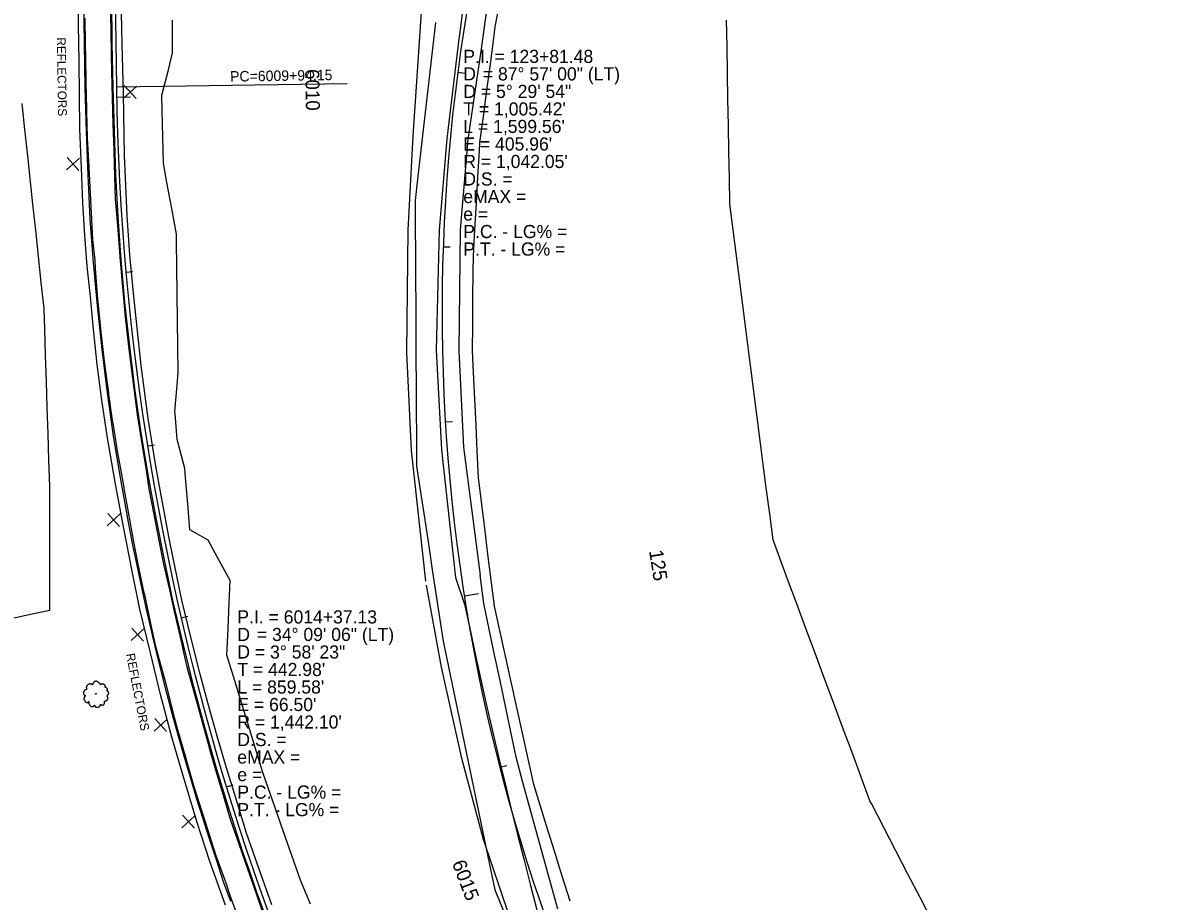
# Model space of a CAD drawing. Extents: x 2132221 to 2141942, y 535736 to 547298.
# Drawn here: x 2138929 to 2139580, y 539779 to 540281 of the extents above; entities that cross this region are included whole.
import ezdxf

# ---------------------------------------------------------------- set-up
doc = ezdxf.new("R2010")
doc.units = 0
for name, color, linetype in [('RD_EX_Conc', 7, 'Continuous'), ('RD_EX_Driveway', 7, 'Continuous'), ('RD_EX_Fence_Other', 7, 'Continuous'), ('RD_EX_Misc', 7, 'Continuous'), ('RD_EX_Misc_txCode', 7, 'Continuous'), ('RD_EX_Road', 7, 'Continuous'), ('RD_EX_VEG', 7, 'Continuous'), ('RD_HC_Cl', 7, 'Continuous'), ('RD_HC_Data', 7, 'Continuous'), ('RD_HC_Data_Tic', 7, 'Continuous'), ('RD_HC_TX_Sta50', 7, 'Continuous'), ('TOPO_E_TLIML-Line', 7, 'Continuous')]:
    doc.layers.add(name, color=color, linetype=linetype)

msp = doc.modelspace()

# ---------------------------------------------------------------- linework, layer by layer
at = {"layer": 'RD_EX_Conc'}
for points in [[(2139047.25, 539779.31), (2139043.17, 539790.54), (2139039.35, 539802.49), (2139034.85, 539815.62), (2139031.4, 539826.42), (2139027.85, 539837.63), (2139024.22, 539850.13), (2139020.67, 539862.18), (2139017.2, 539874.31), (2139013.81, 539886.56), (2139010.8, 539898.23), (2139007.9, 539909.44), (2139004.67, 539922.45), (2139001.65, 539935.51), (2138998.97, 539946.93), (2138996.49, 539958.58), (2138993.81, 539971.26), (2138991.38, 539982.77), (2138988.93, 539995.8), (2138984.43, 540020.27), (2138980.35, 540044.85), (2138976.92, 540069.62), (2138973.88, 540094.48), (2138971.21, 540119.3), (2138968.85, 540144.08), (2138967.01, 540168.84), (2138965.75, 540193.95), (2138964.84, 540218.87), (2138964.17, 540243.73), (2138963.78, 540268.99), (2138963.33, 540293.82)], [(2139066.43, 539772.72), (2139062.22, 539784.49), (2139058.14, 539796.38), (2139054.19, 539807.51), (2139046.48, 539831.19), (2139039.38, 539854.65), (2139032.53, 539878.81), (2139026.07, 539902.54), (2139020.18, 539925.86), (2139014.42, 539950.29), (2139009.36, 539974.37), (2139004.62, 539998.3), (2139000.1, 540022.95), (2138995.99, 540048.15), (2138992.44, 540072.16), (2138989.64, 540096.3), (2138986.8, 540121.15), (2138984.71, 540145.54), (2138982.92, 540170.05), (2138981.64, 540194.31), (2138980.81, 540219.3), (2138980.09, 540244.21), (2138979.59, 540269.04), (2138979.26, 540294.49)]]:
    msp.add_lwpolyline(points, dxfattribs=at)
at = {"layer": 'RD_EX_Driveway'}
for points in [[(2139375.47, 540750.48), (2139341.92, 540703.66), (2139314.26, 540660.24), (2139285.42, 540614.28), (2139260.79, 540569.88), (2139237.27, 540520.32), (2139217.3, 540472.74), (2139203.06, 540422.66), (2139191.88, 540369.74), (2139183.49, 540318.44), (2139176.95, 540267.04), (2139170.52, 540214.7), (2139166.19, 540162.6), (2139164.57, 540093.99), (2139167.47, 540037.05), (2139175.57, 539964.17)], [(2139385.79, 540743), (2139351.72, 540697.27), (2139323.35, 540654.31), (2139295.61, 540608.62), (2139271.39, 540564.02), (2139248.44, 540514.69), (2139230.03, 540468.86), (2139215.27, 540419.42), (2139204.71, 540368.22), (2139197.15, 540317.2), (2139190.28, 540266.06), (2139182.51, 540214.2), (2139178.28, 540162.7), (2139177.46, 540093.75), (2139180.12, 540038.67), (2139189.56, 539965.52)], [(2139234.04, 539774.96), (2139230.04, 539789.4), (2139226.05, 539803.83), (2139222.05, 539818.27), (2139218.06, 539832.71), (2139214.06, 539847.14), (2139210.26, 539861.62), (2139207.16, 539876.24), (2139204.07, 539890.86), (2139200.97, 539905.47), (2139197.88, 539920.09), (2139194.79, 539934.71), (2139191.69, 539949.33), (2139189.56, 539965.52)], [(2139175.57, 539964.17), (2139180.66, 539949.01), (2139183.83, 539934.35), (2139187, 539919.68), (2139190.17, 539905.02), (2139193.5, 539890.4), (2139196.93, 539875.8), (2139200.37, 539861.2), (2139203.8, 539846.59), (2139207.24, 539831.99), (2139210.95, 539817.46), (2139214.66, 539802.93), (2139218.37, 539788.39), (2139222.08, 539773.86)]]:
    msp.add_lwpolyline(points, dxfattribs=at)
at = {"layer": 'RD_EX_Fence_Other'}
for points in [[(2139157.8, 540315.78), (2139154.55, 540267.28), (2139151.12, 540216.15), (2139148.42, 540162.51), (2139147.6, 540092.65), (2139150.15, 540036.8), (2139158.46, 539962.07)], [(2139158.78, 539959.88), (2139167.28, 539913), (2139178.82, 539861.82), (2139191.36, 539814.96), (2139205.94, 539771.49)]]:
    msp.add_lwpolyline(points, dxfattribs=at)
at = {"layer": 'RD_EX_Misc'}
for p, q in [((2138986.2, 540238), (2138993.55, 540244.78)), ((2138986.49, 540245.07), (2138993.27, 540237.72)), ((2138953.51, 540196.91), (2138960.85, 540203.7)), ((2138953.79, 540203.98), (2138960.57, 540196.63)), ((2138976.71, 539993.73), (2138984.06, 540000.51)), ((2138977, 540000.8), (2138983.78, 539993.45)), ((2138990.39, 539928.29), (2138997.74, 539935.07)), ((2138990.68, 539935.35), (2138997.46, 539928)), ((2139003.58, 539876.62), (2139010.93, 539883.4)), ((2139003.87, 539883.68), (2139010.65, 539876.33)), ((2139019.4, 539821.44), (2139026.75, 539828.22)), ((2139019.68, 539828.5), (2139026.46, 539821.16))]:
    msp.add_line(p, q, dxfattribs=at)
for points in [[(2138978.46, 540292.18), (2138978.7, 540277.18), (2138978.95, 540262.18), (2138979.09, 540253.1), (2138979.56, 540238.11), (2138980.02, 540223.12), (2138980.48, 540208.13), (2138980.49, 540207.89), (2138980.95, 540192.89), (2138981.34, 540180.15), (2138982.54, 540165.2), (2138983.73, 540150.25), (2138983.97, 540147.21), (2138985.31, 540132.27), (2138986.65, 540117.33), (2138987.06, 540112.79), (2138988.74, 540097.88), (2138990.13, 540085.53), (2138992.09, 540070.66), (2138994.05, 540055.79), (2138994.14, 540055.11), (2138996.5, 540040.3), (2138998.87, 540025.48), (2139000.56, 540014.88), (2139003.42, 540000.16), (2139006.27, 539985.43), (2139008.92, 539971.82), (2139012.23, 539957.19), (2139015.01, 539944.88), (2139018.32, 539930.25), (2139021.63, 539915.62), (2139022.14, 539913.35), (2139026.13, 539898.89), (2139030.12, 539884.43), (2139034.1, 539869.96), (2139034.94, 539866.9), (2139039.19, 539852.52), (2139043.43, 539838.13), (2139046.93, 539826.29), (2139051.85, 539812.12), (2139056.77, 539797.95), (2139061.69, 539783.78), (2139065.36, 539773.24)], [(2139051.99, 539768.67), (2139046.97, 539782.8), (2139044.53, 539789.69), (2139039.51, 539803.83), (2139039.37, 539804.22), (2139034.78, 539818.5), (2139034.37, 539819.78), (2139030.93, 539830.45), (2139026.49, 539844.27), (2139022.37, 539858.7), (2139021.37, 539862.18), (2139017.25, 539876.6), (2139015.26, 539883.59), (2139011.64, 539898.15), (2139010.17, 539904.07), (2139006.26, 539918.56), (2139004.56, 539924.88), (2139001.68, 539938.02), (2138998.48, 539952.68), (2138997.3, 539958.07), (2138994.51, 539970.82), (2138992, 539984.66), (2138989.32, 539999.42), (2138986.65, 540014.18), (2138986.18, 540016.75), (2138983.5, 540031.5), (2138982.84, 540035.18), (2138980.43, 540049.99), (2138979.75, 540054.13), (2138977.7, 540068.99), (2138977.6, 540069.78), (2138975.55, 540084.64), (2138974.89, 540089.45), (2138973.36, 540104.37), (2138972.94, 540108.39), (2138971.41, 540123.31), (2138971.18, 540125.61), (2138970.11, 540140.57), (2138969.76, 540145.39), (2138968.6, 540157.25), (2138967.81, 540172.23), (2138967.02, 540187.21), (2138966.23, 540202.19), (2138965.54, 540215.21), (2138965.08, 540230.2), (2138965.03, 540231.74), (2138964.76, 540246.74), (2138964.49, 540261.73), (2138964.37, 540268.56), (2138964.09, 540283.56)]]:
    msp.add_lwpolyline(points, dxfattribs=at)
at = {"layer": 'RD_EX_Road'}
for points in [[(2139044.24, 539777.19), (2139035.36, 539802.08), (2139027.81, 539824.93), (2139019.66, 539852.44), (2139013.69, 539873.09), (2139007.2, 539897.4), (2139001.47, 539921.24), (2138995.26, 539946.22), (2138990.97, 539967.91), (2138986.24, 539992.23), (2138981.29, 540018.6), (2138976.77, 540045.15), (2138973.63, 540065.5), (2138971.03, 540085.82), (2138968.64, 540107.92), (2138967.1, 540124.59), (2138965.3, 540141.98), (2138963.96, 540159.44), (2138962.81, 540178.14), (2138962.12, 540198), (2138961.09, 540220.29), (2138960.9, 540239.56), (2138960.75, 540259), (2138960.26, 540279.7), (2138960.46, 540299.46)], [(2139070.67, 539777.4), (2139063.63, 539797.2), (2139056.32, 539818.28), (2139049.32, 539840.94), (2139045.24, 539854.23), (2139039.56, 539873.61), (2139034.15, 539892.69), (2139029.7, 539908.98), (2139024.45, 539930.15), (2139019.27, 539951.25), (2139012.48, 539984.67), (2139007.73, 540010.12), (2139004.32, 540029), (2139000.17, 540055.11), (2138996.01, 540085.19), (2138991.84, 540124.62), (2138989.67, 540148.28), (2138988.17, 540170.98), (2138986.67, 540205.16), (2138985.92, 540240.55), (2138985.3, 540268.71), (2138984.69, 540295.77)]]:
    msp.add_lwpolyline(points, dxfattribs=at)
at = {"layer": 'RD_EX_VEG'}
for points in [[(2139240.91, 539779.47), (2139236.45, 539793.79), (2139232, 539808.12), (2139227.54, 539822.44), (2139223.08, 539836.76), (2139220.2, 539846.03), (2139216.97, 539860.68), (2139213.75, 539875.32), (2139210.52, 539889.97), (2139207.29, 539904.62), (2139204.06, 539919.27), (2139200.83, 539933.92), (2139197.77, 539947.84), (2139195.93, 539962.73), (2139194.09, 539977.61), (2139192.25, 539992.5), (2139190.41, 540007.39), (2139188.69, 540021.32), (2139187.97, 540036.31), (2139187.25, 540051.29), (2139186.53, 540066.27), (2139185.81, 540081.26), (2139185.21, 540093.74), (2139185.36, 540108.74), (2139185.5, 540123.74), (2139185.64, 540138.74), (2139185.73, 540147.97), (2139186.6, 540162.94), (2139187.46, 540177.92), (2139188.33, 540192.89), (2139189.19, 540207.87), (2139189.47, 540212.64), (2139191.46, 540227.5), (2139193.44, 540242.37), (2139195.43, 540257.24), (2139197.41, 540272.11), (2139198.28, 540278.64), (2139201.05, 540293.38)], [(2139092.85, 539777.71), (2139087.08, 539791.38), (2139082.15, 539805.54), (2139077.21, 539819.71), (2139072.28, 539833.87), (2139067.34, 539848.04), (2139065.65, 539852.9), (2139061.25, 539867.24), (2139056.84, 539881.58), (2139052.44, 539895.92), (2139048.04, 539910.26), (2139045.04, 539920.01), (2139045.69, 539935), (2139046.34, 539949.99), (2139046.88, 539962.46), (2139039.72, 539975.65), (2139034.36, 539985.54), (2139023.94, 539991.42), (2139022.72, 540006.37), (2139021.49, 540021.32), (2139021.06, 540026.48), (2139017.26, 540040.99), (2139016.73, 540042.99), (2139015.49, 540057.94), (2139015.4, 540059.03), (2139016.66, 540073.97), (2139017.27, 540081.2), (2139017.07, 540096.2), (2139016.88, 540111.2), (2139016.68, 540126.2), (2139016.49, 540141.2), (2139016.3, 540156.2), (2139016.25, 540160.2), (2139013.54, 540174.95), (2139010.83, 540189.7), (2139008.79, 540200.84), (2139008.48, 540215.83), (2139008.17, 540230.83), (2139007.98, 540239.58), (2139011.61, 540254.14), (2139014.03, 540263.86), (2139014.03, 540278.86), (2139014.03, 540282.49)], [(2139164.09, 540281.07), (2139162.39, 540266.16), (2139160.69, 540251.26), (2139159, 540236.36), (2139157.3, 540221.45), (2139155.6, 540206.55), (2139153.91, 540191.65), (2139152.52, 540179.47), (2139152.6, 540164.47), (2139152.67, 540149.47), (2139152.74, 540134.47), (2139152.82, 540119.47), (2139152.89, 540104.47), (2139152.97, 540089.47), (2139153.04, 540074.47), (2139153.12, 540059.47), (2139153.19, 540044.47), (2139153.27, 540029.47), (2139153.27, 540027.89), (2139155.53, 540013.06), (2139157.79, 539998.23), (2139160.05, 539983.4), (2139162.31, 539968.57), (2139164.57, 539953.75), (2139166.83, 539938.92), (2139168.5, 539927.95), (2139171.54, 539913.26), (2139174.59, 539898.57), (2139177.63, 539883.89), (2139180.68, 539869.2), (2139183.72, 539854.51), (2139186.77, 539839.82), (2139189.82, 539825.14), (2139192.86, 539810.45), (2139195.91, 539795.76), (2139197.96, 539785.86), (2139203.68, 539771.99)], [(2138920.87, 539940.65), (2138935.53, 539943.82), (2138943.94, 539945.64), (2138943.94, 539960.64), (2138943.94, 539975.64), (2138943.94, 539990.64), (2138943.94, 540005.64), (2138943.94, 540016.25), (2138943.46, 540031.24), (2138942.97, 540046.23), (2138942.49, 540061.23), (2138942.01, 540076.22), (2138941.52, 540091.21), (2138941.04, 540106.2), (2138940.67, 540117.73), (2138939.07, 540132.64), (2138937.48, 540147.56), (2138935.88, 540162.47), (2138934.29, 540177.39), (2138932.92, 540190.14), (2138931.33, 540205.06), (2138929.73, 540219.97), (2138928.14, 540234.89)]]:
    msp.add_lwpolyline(points, dxfattribs=at)
for centre, radius in [((2138970.25, 539897.83), 0.25), ((2138970.23, 539897.83), 0.0001)]:
    msp.add_circle(centre, radius, dxfattribs=at)
for points in [[(2138975.61, 539902.59), (2138975.42, 539902.82), (2138975.13, 539903), (2138974.89, 539903.11), (2138974.68, 539903.23), (2138974.46, 539903.32), (2138974.12, 539903.43), (2138973.82, 539903.46), (2138973.56, 539903.38), (2138973.36, 539903.26), (2138973.12, 539903.11), (2138972.99, 539903), (2138972.89, 539903.07), (2138972.81, 539903.2), (2138972.69, 539903.43), (2138972.52, 539903.62), (2138972.35, 539903.8), (2138972.1, 539904.04), (2138971.86, 539904.3), (2138971.64, 539904.47), (2138971.38, 539904.67), (2138971.03, 539904.86), (2138970.71, 539905.03), (2138970.32, 539905.09), (2138969.8, 539904.95), (2138969.46, 539904.8), (2138969.17, 539904.74), (2138968.94, 539904.33), (2138968.8, 539903.96), (2138968.67, 539903.81), (2138968.41, 539903.47), (2138968.32, 539903.24), (2138968.25, 539903.01), (2138968.18, 539903.05), (2138967.89, 539903.29), (2138967.62, 539903.45), (2138967.16, 539903.61), (2138966.85, 539903.62), (2138966.54, 539903.47), (2138966.26, 539903.25), (2138966.05, 539903.19), (2138965.8, 539903.06), (2138965.72, 539903.03), (2138965.45, 539902.85), (2138965.19, 539902.47), (2138964.95, 539902.21), (2138964.87, 539901.97), (2138964.84, 539901.74), (2138964.77, 539901.44), (2138964.88, 539901), (2138965.03, 539900.69), (2138965.14, 539900.52), (2138964.66, 539900.31), (2138964.37, 539900.11), (2138963.99, 539899.94), (2138963.93, 539899.88), (2138963.55, 539899.6), (2138963.41, 539899.27), (2138963.19, 539898.96), (2138963.14, 539898.68), (2138963.11, 539898.27), (2138963.16, 539897.88), (2138963.41, 539897.43), (2138963.7, 539897.15), (2138964.21, 539896.85), (2138964.44, 539896.72), (2138964.29, 539896.62), (2138964.03, 539896.34), (2138963.72, 539896.06), (2138963.58, 539895.73), (2138963.45, 539895.47), (2138963.37, 539895.19), (2138963.42, 539894.79), (2138963.64, 539894.45), (2138963.82, 539894.04), (2138964.06, 539893.65), (2138964.38, 539893.27), (2138964.9, 539892.93), (2138965.18, 539892.81), (2138965.38, 539892.86), (2138965.79, 539892.96), (2138965.92, 539893.15), (2138966.38, 539893.54), (2138966.32, 539893.35), (2138966.18, 539892.98), (2138966.29, 539892.41), (2138966.44, 539892), (2138966.65, 539891.55), (2138966.8, 539891.28), (2138967.17, 539890.98), (2138967.48, 539890.75), (2138967.83, 539890.56), (2138968.23, 539890.53), (2138968.55, 539890.59), (2138968.79, 539890.74), (2138969.12, 539890.93), (2138969.28, 539891.02)], [(2138969.28, 539891.02), (2138969.36, 539891.19), (2138969.51, 539891.4), (2138969.54, 539891.32), (2138969.62, 539891.16), (2138969.72, 539890.87), (2138969.81, 539890.66), (2138970.05, 539890.44), (2138970.31, 539890.3), (2138970.82, 539890.16), (2138971.35, 539890.28), (2138971.83, 539890.35), (2138972.12, 539890.51), (2138972.25, 539890.7), (2138972.61, 539891.06), (2138972.65, 539891.37), (2138972.71, 539891.49), (2138972.94, 539891.84), (2138973.03, 539891.82), (2138973.25, 539891.65), (2138973.59, 539891.46), (2138973.87, 539891.34), (2138974.15, 539891.29), (2138974.37, 539891.39), (2138974.65, 539891.68), (2138974.98, 539891.91), (2138975.03, 539892.07), (2138975.08, 539892.25), (2138975.17, 539892.44), (2138975.18, 539892.65), (2138975.22, 539892.82), (2138975.23, 539892.96), (2138975.26, 539893.16), (2138975.23, 539893.37), (2138975.17, 539893.52), (2138975.24, 539893.65), (2138975.49, 539893.68), (2138975.6, 539893.71), (2138975.78, 539893.84), (2138976.19, 539893.91), (2138976.52, 539894.15), (2138976.8, 539894.47), (2138976.96, 539894.7), (2138977.07, 539894.99), (2138977.11, 539895.31), (2138977.16, 539895.52), (2138977.13, 539895.73), (2138977, 539896.06), (2138976.87, 539896.27), (2138976.63, 539896.53), (2138976.53, 539896.71), (2138976.59, 539896.73), (2138976.7, 539896.83), (2138976.9, 539897.02), (2138977.18, 539897.38), (2138977.45, 539897.82), (2138977.47, 539897.84), (2138977.58, 539898.08), (2138977.58, 539898.39), (2138977.53, 539898.58), (2138977.49, 539898.81), (2138977.34, 539899.01), (2138977.13, 539899.23), (2138976.91, 539899.4), (2138976.7, 539899.48), (2138976.49, 539899.53), (2138976.55, 539899.68), (2138976.7, 539899.96), (2138976.78, 539900.1), (2138976.81, 539900.33), (2138976.8, 539900.63), (2138976.59, 539901.04), (2138976.11, 539901.45), (2138975.76, 539901.54), (2138975.53, 539901.53), (2138975.59, 539901.65), (2138975.6, 539901.93), (2138975.66, 539902.12), (2138975.63, 539902.34), (2138975.61, 539902.52), (2138975.58, 539902.62)]]:
    msp.add_spline(points, degree=3, dxfattribs=at)
at = {"layer": 'RD_HC_Cl'}
msp.add_line((2138963.01, 541675.46), (2138981.93, 540244.3), dxfattribs=at)
for centre, radius, start, end in [((2140209.98, 540116.6), 1042.05, 127.19072, 215.14072), ((2140423.86, 540266.28), 1442.1, 180.87321, 215.0249)]:
    msp.add_arc(centre, radius, start, end, dxfattribs=at)
at = {"layer": 'RD_HC_Data'}
msp.add_line((2138981.93, 540244.3), (2139113.72, 540246.31), dxfattribs=at)
at = {"layer": 'RD_HC_Data_Tic'}
for p, q in [((2139176.86, 540252.72), (2139180.83, 540252.2)), ((2138982.03, 540238.45), (2138990.03, 540238.61)), ((2139168.57, 540153.11), (2139172.57, 540152.97)), ((2138987.42, 540138.62), (2138991.4, 540138.97)), ((2139169.87, 540053.15), (2139173.86, 540053.4)), ((2138999.72, 540039.4), (2139003.67, 540040.03)), ((2139180.73, 539953.78), (2139188.63, 539955.03)), ((2139018.86, 539941.27), (2139022.76, 539942.17)), ((2139201.07, 539855.91), (2139204.94, 539856.91)), ((2139044.76, 539844.7), (2139048.58, 539845.87))]:
    msp.add_line(p, q, dxfattribs=at)
at = {"layer": 'TOPO_E_TLIML-Line'}
msp.add_lwpolyline([(2139447.67, 539768.23), (2139440.76, 539781.55), (2139433.85, 539794.86), (2139426.95, 539808.18), (2139420.04, 539821.49), (2139413.13, 539834.8), (2139412.14, 539836.7), (2139406.92, 539850.76), (2139401.7, 539864.83), (2139396.48, 539878.89), (2139391.26, 539892.95), (2139386.04, 539907.01), (2139380.81, 539921.07), (2139375.59, 539935.14), (2139370.37, 539949.2), (2139365.15, 539963.26), (2139359.93, 539977.32), (2139356.81, 539985.73), (2139354.9, 540000.61), (2139352.98, 540015.49), (2139351.07, 540030.37), (2139349.15, 540045.24), (2139347.24, 540060.12), (2139345.33, 540075), (2139343.41, 540089.88), (2139341.5, 540104.75), (2139339.59, 540119.63), (2139337.67, 540134.51), (2139335.76, 540149.39), (2139333.85, 540164.26), (2139332.16, 540177.35), (2139331.9, 540192.35), (2139331.63, 540207.34), (2139331.37, 540222.34), (2139331.1, 540237.34), (2139330.83, 540252.34), (2139330.57, 540267.33), (2139330.3, 540282.33)], dxfattribs=at)

# ---------------------------------------------------------------- texts
at = {"layer": 'RD_EX_Misc_txCode'}
for rotation, p in [(270.90963, (2138947.97, 540272.53)), (280.92314, (2138987.44, 539920.5))]:
    msp.add_text('REFLECTORS', height=5, rotation=rotation, dxfattribs=at).set_placement(p)
at = {"layer": 'RD_HC_Data'}
for s, p in [('P.I. = 123+81.48', (2139180, 540258)), ('D', (2139180, 540248)), ('    = 87%%d 57\' 00" (LT)', (2139180, 540248)), ('D = 5%%d 29\' 54"', (2139180, 540238)), ("T = 1,005.42'", (2139180, 540228)), ("L = 1,599.56'", (2139180, 540218)), ("E = 405.96'", (2139180, 540208)), ("R = 1,042.05'", (2139180, 540198)), ('D.S. = ', (2139180, 540188)), ('eMAX = ', (2139180, 540178)), ('e = ', (2139180, 540168)), ('P.C. - LG% = ', (2139180, 540158)), ('P.T. - LG% = ', (2139180, 540148)), ('P.I. = 6014+37.13', (2139051, 539938)), ('D', (2139051, 539928)), ('    = 34%%d 09\' 06" (LT)', (2139051, 539928)), ('D = 3%%d 58\' 23"', (2139051, 539918)), ("T = 442.98'", (2139051, 539908)), ("L = 859.58'", (2139051, 539898)), ("E = 66.50'", (2139051, 539888)), ("R = 1,442.10'", (2139051, 539878)), ('D.S. = ', (2139051, 539868)), ('eMAX = ', (2139051, 539858)), ('e = ', (2139051, 539848)), ('P.C. - LG% = ', (2139051, 539838)), ('P.T. - LG% = ', (2139051, 539828))]:
    msp.add_text(s, height=7.5, dxfattribs=at).set_placement(p)
msp.add_text('PC=6009+94.15', height=6, rotation=0.87321, dxfattribs=at).set_placement((2139046.89, 540247.29))
at = {"layer": 'RD_HC_TX_Sta50'}
for s, rotation, p in [('6010', 271.10563, (2139089.74, 540254.44)), ('125', 278.989, (2139286.01, 539979.46)), ('6015', 290.97097, (2139173.38, 539801.21))]:
    msp.add_text(s, height=8, rotation=rotation, dxfattribs=at).set_placement(p)

doc.saveas('drawing.dxf')
